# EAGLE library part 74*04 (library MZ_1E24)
Hex INVERTER
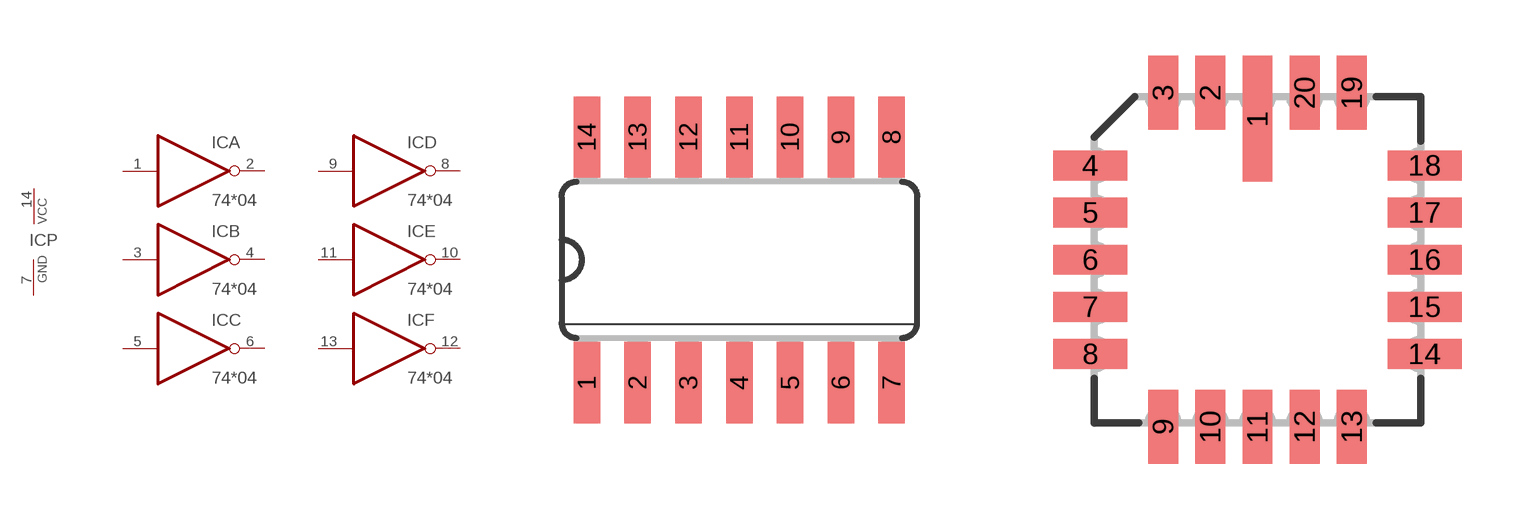
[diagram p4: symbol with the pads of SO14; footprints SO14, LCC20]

Designator prefix IC; gates A=EU_7404 B=EU_7404 C=EU_7404 D=EU_7404 E=EU_7404 F=EU_7404 P=MZ_1E18_V1_74XX-EU_PWRN

## 7404D, 74AC04D, 74ACT04D, 74ALS04D, 74AS04D, 74HC04D, 74HCT04D, 74LS04D, 74S04D  [SO14]
1  A:I  in
2  A:O  out
3  B:I  in
4  B:O  out
5  C:I  in
6  C:O  out
7  P:GND  pwr
8  D:O  out
9  D:I  in
10  E:O  out
11  E:I  in
12  F:O  out
13  F:I  in
14  P:VCC  pwr

## 7404FK, 74AC04FK, 74ACT04FK, 74HC04FK, 74HCT04FK, 74LS04FK, 74S04FK  [LCC20]
2  A:I  in
3  A:O  out
4  B:I  in
6  B:O  out
8  C:I  in
9  C:O  out
10  P:GND  pwr
12  D:O  out
13  D:I  in
14  E:O  out
16  E:I  in
18  F:O  out
19  F:I  in
20  P:VCC  pwr

## 7404N, 74AC04N, 74ACT04N, 74ALS04N, 74AS04N, 74HC04N, 74HCT04N, 74LS04N, 74S04N  [EU_DIL14]
Pads as for SO14

## Footprint SO14 (pad centres in mm)
Small Outline package 150 mil
smd 0.66 x 2.032: 1 -3.81,-3.073; 2 -2.54,-3.073; 3 -1.27,-3.073; 4 0,-3.073; 5 1.27,-3.073; 6 2.54,-3.073; 7 3.81,-3.073; 8 3.81,3.073; 9 2.54,3.073; 10 1.27,3.073; 11 0,3.073; 12 -1.27,3.073; 13 -2.54,3.073; 14 -3.81,3.073

## Footprint LCC20 (pad centres in mm)
Leadless Chip Carrier Ceramic Package
smd 0.8 x 3.4: 1 0,3.8
smd 0.8 x 2: 2 -1.27,4.5; 3 -2.54,4.5; 9 -2.54,-4.5; 10 -1.27,-4.5; 11 0,-4.5; 12 1.27,-4.5; 13 2.54,-4.5; 19 2.54,4.5; 20 1.27,4.5
smd 2 x 0.8: 4 -4.5,2.54; 5 -4.5,1.27; 6 -4.5,0; 7 -4.5,-1.27; 8 -4.5,-2.54; 14 4.5,-2.54; 15 4.5,-1.27; 16 4.5,0; 17 4.5,1.27; 18 4.5,2.54

## Footprint EU_DIL14 (pad centres in mm)
Dual In Line Package
drill 0.813 round: 1 -7.62,-3.81; 2 -5.08,-3.81; 3 -2.54,-3.81; 4 0,-3.81; 5 2.54,-3.81; 6 5.08,-3.81; 7 7.62,-3.81; 8 7.62,3.81; 9 5.08,3.81; 10 2.54,3.81; 11 0,3.81; 12 -2.54,3.81; 13 -5.08,3.81; 14 -7.62,3.81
